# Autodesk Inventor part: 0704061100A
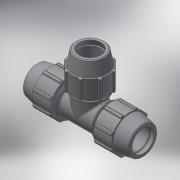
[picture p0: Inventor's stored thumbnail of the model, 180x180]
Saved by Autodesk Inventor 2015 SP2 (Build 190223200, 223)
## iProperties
Created: 2017-02
Part Number: 0704061100A
Material: Generic
Description: PLASSON TEE 110-110-110
Document SubType Name: Modeling
Designer: KIM
Mass: 2642.84 g
Surface Area: 3396.39 cm^2
Volume: 2642.84 cm^3
Density: 1 g/cm^3
Appearance: Default
Author: KIM
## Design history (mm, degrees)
derived "87040.ipt"
feature "Solid1::87040.ipt"
tag "TaggingFeature1"
body "Solid1"
other parameters: "d4" = 24.33333, "d5" = 73, "d7" = 181, "d13" = 120 deg, "d14" = 143, "d15" = 8 deg, "d18" = 5.5, "d19" = 35 deg, "d20" = 17.5 deg, "d21" = 168.33, "d23" = 0, "d25" = 360 deg, "d27" = 3.62, "d42" = 102.2, "d43" = 5.43, "d46" = 3.3, "d63" = 194, "d67" = 135.75, "d77" = 181, "d78" = 8 deg, "d79" = 292, "d80" = 120 deg, "d81" = 143, "d82" = 24.33333, "d85" = 135.75, "d87" = 9.73333, "d88" = 9.73333, "d89" = 73, "d90" = 102.2, "d98" = 168.33, "d99" = 35 deg, "d100" = 17.5 deg, "d102" = 0, "d103" = 3.62, "d107" = 360 deg, "d109" = 3.3, "d112" = 5.5, "d118" = 360 deg, "d121" = 0, "d128" = 583, "d131" = 99, "d132" = 99, "d133" = 194, "d134" = 3.88, "d152" = 0, "d154" = 0, "d156" = 0, "d158" = 0, "d163" = 15.66667, "d165" = 18.9, "d166" = 128.9625, "d167" = 128.9625, "d168" = 3.78, "d169" = 149.325, "d170" = 1.89, "d171" = 6.615, "d172" = 142.5375, "d173" = 4.7, "d174" = 3.91667, "d175" = 3.525, "d176" = 2.2, "d177" = 5.5, "E_" = 181, "A_" = 292, "l_" = 194, "H_" = 583, "d162" = 18.8, "d164" = 22.68
